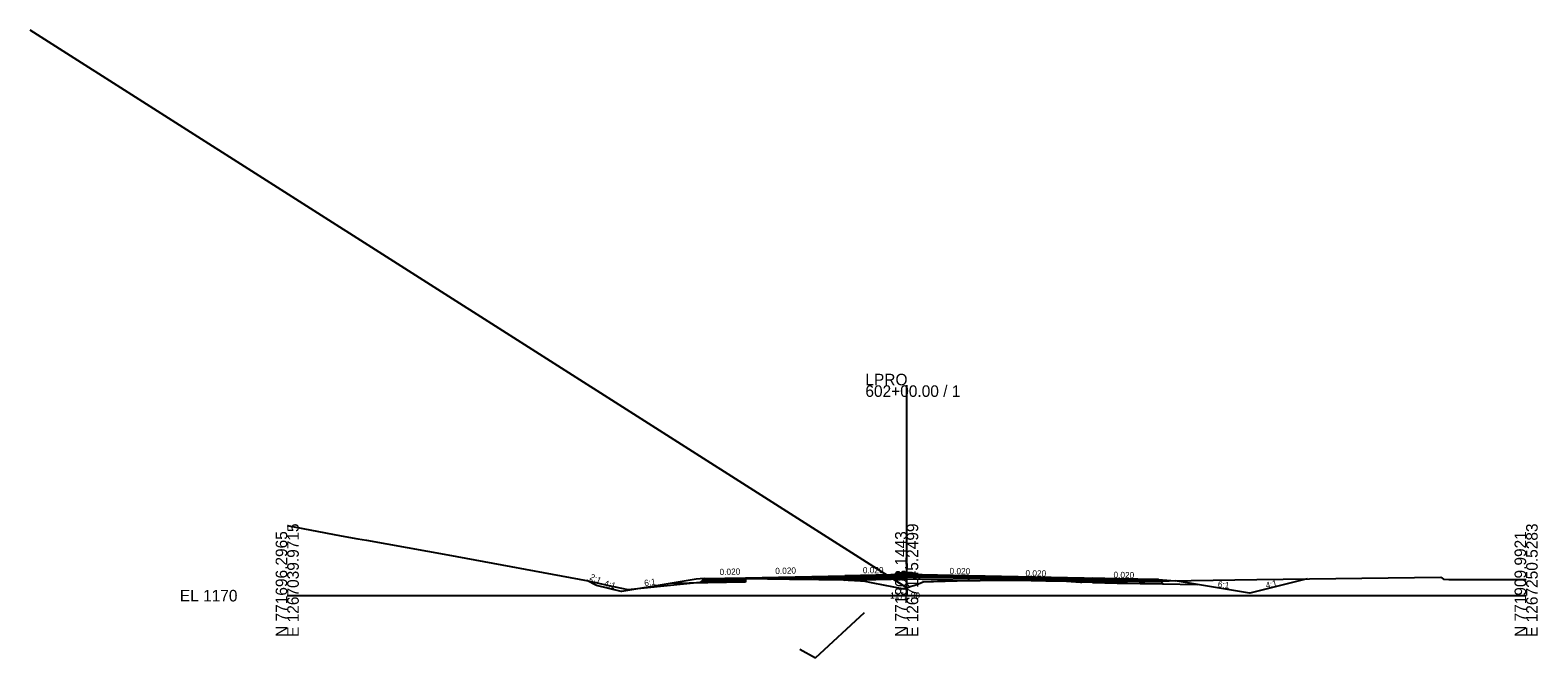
# Model space of a CAD drawing. Extents: x -3833 to 1267678, y -522 to 773248.
# Drawn here: x 937.8 to 1302.8, y 2984.9 to 3137 of the extents above; entities that cross this region are included whole.
import ezdxf

# ---------------------------------------------------------------- set-up
doc = ezdxf.new("R2010")
doc.units = 0
for name, color, linetype in [('Exist Cross Section Cell', 7, 'Continuous'), ('Exist XS Center Line Elevation Label', 7, 'Continuous'), ('Exist XS Ground Line', 7, 'Continuous'), ('Prop CMT DNC', 7, 'Continuous'), ('Prop CMT Pvmt Course 1', 7, 'Continuous'), ('Prop CMT Pvmt Course 2', 7, 'Continuous'), ('Prop CMT Pvmt Course 3', 7, 'Continuous'), ('Prop CMT Pvmt Course 4', 7, 'Continuous'), ('Prop CMT Shld Paved Course 1', 7, 'Continuous'), ('Prop CMT Shld Paved Course 2', 7, 'Continuous'), ('Prop CMT Shld Paved Course 4', 7, 'Continuous'), ('Prop CMT Slope Grass', 7, 'Continuous'), ('Prop CMT Subgrade Earthwork', 7, 'Continuous'), ('Prop Conc Curb and Gutter', 7, 'Continuous'), ('Prop Corridor Mesh Bottom', 7, 'Continuous'), ('Prop XS Ditch Slope Text', 7, 'Continuous'), ('Prop XS Finish Grade', 7, 'Continuous'), ('Prop XS SE Text', 7, 'Continuous'), ('Scratch_Level_1', 7, 'Continuous'), ('Scratch_Level_5', 7, 'Continuous')]:
    doc.layers.add(name, color=color, linetype=linetype)

msp = doc.modelspace()

# ---------------------------------------------------------------- linework, layer by layer
at = {"layer": 'Exist Cross Section Cell'}
for p, q in [((1150, 3000), (1150, 3050.94)), ((1000, 3000), (1150, 3000)), ((1150, 3000), (1300, 3000))]:
    msp.add_line(p, q, dxfattribs=at)
at = {"layer": 'Exist XS Ground Line'}
for p, q in [((1000, 3016.98), (1013.1, 3014.52)), ((1013.1, 3014.52), (1017.12, 3013.79)), ((1017.12, 3013.79), (1019.2, 3013.47)), ((1019.2, 3013.47), (1038.86, 3009.86)), ((1038.86, 3009.86), (1072.85, 3003.6)), ((1072.85, 3003.6), (1077.84, 3002.43)), ((1077.84, 3002.43), (1082.49, 3001.48)), ((1082.49, 3001.48), (1100.75, 3003.38)), ((1100.75, 3003.38), (1104.96, 3003.76)), ((1104.96, 3003.76), (1106.21, 3003.95)), ((1106.21, 3003.95), (1106.62, 3003.97)), ((1106.62, 3003.97), (1111, 3004.18)), ((1111, 3004.18), (1121.63, 3004.03)), ((1121.63, 3004.03), (1122.75, 3004.01)), ((1122.75, 3004.01), (1134.73, 3003.8)), ((1134.73, 3003.8), (1135.81, 3003.77)), ((1135.81, 3003.77), (1138.81, 3003.63)), ((1138.81, 3003.63), (1139.44, 3003.57)), ((1139.44, 3003.57), (1141.84, 3003.14)), ((1141.84, 3003.14), (1149.34, 3001.69)), ((1149.34, 3001.69), (1150, 3001.9)), ((1150, 3001.9), (1151.1, 3002.26)), ((1151.1, 3002.26), (1151.76, 3002.45)), ((1151.76, 3002.45), (1152.86, 3002.88)), ((1152.86, 3002.88), (1154.02, 3003.31)), ((1154.02, 3003.31), (1155.92, 3003.4)), ((1155.92, 3003.4), (1156.46, 3003.42)), ((1156.46, 3003.42), (1162.26, 3003.57)), ((1162.26, 3003.57), (1164.74, 3003.64)), ((1164.74, 3003.64), (1167.77, 3003.67)), ((1167.77, 3003.67), (1176.6, 3003.75)), ((1176.6, 3003.75), (1183.66, 3003.59)), ((1183.66, 3003.59), (1188.69, 3003.48)), ((1188.69, 3003.48), (1192.07, 3003.27)), ((1192.07, 3003.27), (1192.42, 3003.25)), ((1192.42, 3003.25), (1234.82, 3003.9)), ((1234.82, 3003.9), (1279.31, 3004.46)), ((1279.31, 3004.46), (1279.96, 3003.96)), ((1279.96, 3003.96), (1281.26, 3003.94)), ((1281.26, 3003.94), (1284.65, 3003.94)), ((1284.65, 3003.94), (1284.99, 3003.94)), ((1284.99, 3003.94), (1300, 3003.93))]:
    msp.add_line(p, q, dxfattribs=at)
at = {"layer": 'Prop CMT Pvmt Course 1'}
for p, q in [((1111, 3004.34), (1135, 3004.82)), ((1135, 3004.82), (1135, 3004.82)), ((1135, 3004.82), (1135, 3004.82)), ((1135, 3004.82), (1135, 3004.57)), ((1146.95, 3005.06), (1146.2, 3005.04)), ((1146.2, 3005.04), (1146.2, 3004.79)), ((1146.2, 3005.04), (1146.2, 3005.04)), ((1146.2, 3004.79), (1146.95, 3004.81)), ((1146.2, 3004.79), (1146.2, 3004.79)), ((1146.95, 3004.81), (1146.95, 3005.06)), ((1152.25, 3004.82), (1152.25, 3005.07)), ((1152.25, 3005.07), (1152.82, 3005.06)), ((1152.82, 3004.81), (1152.25, 3004.82)), ((1152.82, 3005.06), (1153, 3005.06)), ((1153, 3004.81), (1152.82, 3004.81)), ((1153, 3005.06), (1153, 3004.81)), ((1201, 3004.1), (1165, 3004.82)), ((1165, 3004.82), (1165, 3004.82)), ((1165, 3004.82), (1165, 3004.82)), ((1165, 3004.82), (1165, 3004.57)), ((1135, 3004.57), (1111, 3004.09)), ((1111, 3004.09), (1111, 3004.34)), ((1111, 3004.34), (1111, 3004.34)), ((1135, 3004.57), (1135, 3004.57)), ((1165, 3004.57), (1195, 3003.97)), ((1165, 3004.57), (1165, 3004.57)), ((1195, 3004.22), (1195, 3003.97)), ((1201, 3004.1), (1195, 3004.22)), ((1195, 3003.97), (1195, 3004.22)), ((1195, 3004.22), (1195, 3004.22)), ((1195, 3004.22), (1195, 3004.22)), ((1195, 3004.22), (1201, 3004.1)), ((1195, 3003.97), (1201, 3003.85)), ((1201, 3003.85), (1201, 3004.1))]:
    msp.add_line(p, q, dxfattribs=at)
at = {"layer": 'Prop CMT Pvmt Course 2'}
for p, q in [((1150, 3004.87), (1135, 3004.57)), ((1146.95, 3004.81), (1146.2, 3004.79)), ((1146.2, 3004.79), (1146.2, 3004.54)), ((1146.2, 3004.79), (1146.2, 3004.79)), ((1146.95, 3004.56), (1146.95, 3004.81)), ((1165, 3004.57), (1150, 3004.87)), ((1150, 3004.87), (1150, 3004.87)), ((1150, 3004.87), (1150, 3004.87)), ((1152.25, 3004.57), (1152.25, 3004.82)), ((1152.25, 3004.82), (1152.82, 3004.81)), ((1152.82, 3004.81), (1153, 3004.81)), ((1153, 3004.81), (1153, 3004.56)), ((1135, 3004.57), (1135, 3004.57)), ((1135, 3004.57), (1135, 3004.24)), ((1135, 3004.24), (1150, 3004.54)), ((1135, 3004.24), (1135, 3004.24)), ((1146.2, 3004.54), (1146.2, 3004.54)), ((1150, 3004.54), (1150, 3004.54)), ((1150, 3004.54), (1150, 3004.54)), ((1150, 3004.54), (1165, 3004.24)), ((1165, 3004.24), (1165, 3004.57)), ((1165, 3004.57), (1165, 3004.57)), ((1165, 3004.24), (1165, 3004.24)), ((1195, 3003.97), (1195, 3003.64)), ((1201, 3003.85), (1195, 3003.97)), ((1195, 3003.64), (1201, 3003.52)), ((1201, 3003.52), (1201, 3003.85))]:
    msp.add_line(p, q, dxfattribs=at)
at = {"layer": 'Prop CMT Pvmt Course 3'}
for p, q in [((1146.2, 3004.54), (1146.2, 3004.17)), ((1146.2, 3004.54), (1146.2, 3004.54)), ((1146.2, 3004.17), (1146.2, 3004.17)), ((1146.95, 3004.18), (1146.95, 3004.56)), ((1152.25, 3004.2), (1152.25, 3004.57)), ((1153, 3004.56), (1153, 3004.18))]:
    msp.add_line(p, q, dxfattribs=at)
at = {"layer": 'Prop CMT Pvmt Course 4'}
for p, q in [((1135, 3003.78), (1150.01, 3004.08)), ((1135, 3003.78), (1135, 3003.79)), ((1146.2, 3004.17), (1146.2, 3004)), ((1146.2, 3004.17), (1146.2, 3004.17)), ((1146.95, 3004.02), (1146.95, 3004.18)), ((1149.99, 3004.08), (1165, 3003.78)), ((1152.25, 3004.03), (1152.25, 3004.2)), ((1153, 3004.18), (1153, 3004.02)), ((1195, 3003.64), (1195, 3003.18)), ((1201, 3003.52), (1195, 3003.64)), ((1195, 3003.18), (1201, 3003.06)), ((1201, 3003.06), (1201, 3003.52))]:
    msp.add_line(p, q, dxfattribs=at)
at = {"layer": 'Prop CMT Shld Paved Course 1'}
for p, q in [((1150, 3005.12), (1135, 3004.82)), ((1135, 3004.57), (1150, 3004.87)), ((1135, 3004.82), (1135, 3004.82)), ((1135, 3004.82), (1135, 3004.57)), ((1149.99, 3005.16), (1149.99, 3005.16)), ((1149.99, 3005.16), (1149.99, 3005.16)), ((1149.99, 3004.91), (1149.99, 3004.91)), ((1165, 3004.82), (1150, 3005.12)), ((1150, 3005.12), (1150, 3005.12)), ((1150, 3005.12), (1150, 3005.12)), ((1150, 3004.87), (1150, 3004.87)), ((1150, 3004.87), (1150, 3004.87)), ((1150, 3004.87), (1165, 3004.57)), ((1165, 3004.57), (1165, 3004.82)), ((1165, 3004.82), (1165, 3004.82)), ((1100.74, 3003.88), (1101, 3004.14)), ((1111, 3004.09), (1100.74, 3003.88)), ((1101, 3004.14), (1111, 3004.34)), ((1101, 3004.14), (1101, 3004.14)), ((1111, 3004.34), (1111, 3004.34)), ((1111, 3004.34), (1111, 3004.34)), ((1111, 3004.34), (1111, 3004.09)), ((1111, 3004.09), (1111, 3004.09)), ((1201, 3004.1), (1201, 3003.85)), ((1211, 3003.9), (1201, 3004.1)), ((1201, 3003.85), (1211.26, 3003.64)), ((1211.26, 3003.64), (1211, 3003.9))]:
    msp.add_line(p, q, dxfattribs=at)
at = {"layer": 'Prop CMT Shld Paved Course 2'}
for p, q in [((1100.4, 3003.54), (1100.74, 3003.88)), ((1111, 3003.76), (1100.4, 3003.54)), ((1100.74, 3003.88), (1111, 3004.09)), ((1100.74, 3003.88), (1100.74, 3003.88)), ((1121.63, 3004.3), (1111, 3004.09)), ((1111, 3004.09), (1113.78, 3004.14)), ((1111, 3004.09), (1111, 3004.09)), ((1111, 3004.09), (1111, 3004.09)), ((1111, 3004.09), (1111, 3003.76)), ((1111, 3004.09), (1111, 3004.09)), ((1111, 3004.09), (1111, 3004.09)), ((1111, 3004.09), (1111, 3004.09)), ((1111, 3003.76), (1111, 3003.76)), ((1113.78, 3004.14), (1113.78, 3004.14)), ((1113.78, 3004.14), (1113.78, 3004.14)), ((1113.78, 3004.14), (1121.63, 3004.03)), ((1122.75, 3004.32), (1121.63, 3004.3)), ((1121.63, 3004.3), (1121.63, 3004.3)), ((1121.63, 3004.03), (1121.63, 3004.03)), ((1121.63, 3004.03), (1122.75, 3004.01)), ((1134.73, 3004.56), (1122.75, 3004.32)), ((1122.75, 3004.32), (1122.75, 3004.32)), ((1122.75, 3004.01), (1123.37, 3004)), ((1123.37, 3004), (1134.73, 3004.23)), ((1123.37, 3004), (1123.37, 3004)), ((1123.37, 3004), (1123.37, 3004)), ((1135, 3004.57), (1134.73, 3004.56)), ((1134.73, 3004.56), (1134.73, 3004.56)), ((1134.73, 3004.23), (1135, 3004.24)), ((1134.73, 3004.23), (1134.73, 3004.23)), ((1135, 3003.78), (1135, 3004.57)), ((1135, 3004.57), (1135, 3004.57)), ((1167.77, 3004.51), (1165, 3004.57)), ((1165, 3004.57), (1165, 3004.57)), ((1165, 3004.57), (1165, 3003.78)), ((1165, 3004.24), (1167.77, 3004.18)), ((1176.6, 3004.34), (1167.77, 3004.51)), ((1167.77, 3004.51), (1167.77, 3004.51)), ((1167.77, 3004.18), (1167.77, 3004.18)), ((1167.77, 3004.18), (1176.6, 3004)), ((1183.66, 3004.2), (1176.6, 3004.34)), ((1176.6, 3004.34), (1176.6, 3004.34)), ((1176.6, 3004), (1176.6, 3004)), ((1176.6, 3004), (1183.66, 3003.86)), ((1188.69, 3004.09), (1183.66, 3004.2)), ((1183.66, 3004.2), (1183.66, 3004.2)), ((1183.66, 3003.86), (1183.66, 3003.86)), ((1183.66, 3003.86), (1188.69, 3003.76)), ((1192.07, 3004.03), (1188.69, 3004.09)), ((1188.69, 3004.09), (1188.69, 3004.09)), ((1188.69, 3004.09), (1188.69, 3004.09)), ((1188.69, 3003.76), (1188.69, 3003.76)), ((1188.69, 3003.76), (1188.69, 3003.76)), ((1188.69, 3003.76), (1192.07, 3003.69)), ((1192.42, 3004.02), (1192.07, 3004.03)), ((1192.07, 3004.03), (1192.07, 3004.03)), ((1192.07, 3003.69), (1192.07, 3003.69)), ((1192.07, 3003.69), (1192.42, 3003.69)), ((1195, 3003.97), (1192.42, 3004.02)), ((1192.42, 3004.02), (1192.42, 3004.02)), ((1192.42, 3003.69), (1192.42, 3003.69)), ((1192.42, 3003.69), (1195, 3003.64)), ((1195, 3003.64), (1195, 3003.97)), ((1195, 3003.97), (1195, 3003.97)), ((1201, 3003.85), (1201, 3003.52)), ((1211.26, 3003.64), (1201, 3003.85)), ((1201, 3003.52), (1211.59, 3003.31)), ((1211.59, 3003.31), (1211.26, 3003.64))]:
    msp.add_line(p, q, dxfattribs=at)
at = {"layer": 'Prop CMT Shld Paved Course 4'}
for p, q in [((1099.94, 3003.08), (1100.4, 3003.54)), ((1111, 3003.3), (1099.94, 3003.08)), ((1100.4, 3003.54), (1100.9, 3003.55)), ((1100.9, 3003.55), (1111, 3003.76)), ((1111, 3003.76), (1111, 3003.3)), ((1201, 3003.52), (1201, 3003.06)), ((1211.09, 3003.32), (1201, 3003.52)), ((1201, 3003.06), (1212.06, 3002.84)), ((1211.59, 3003.31), (1211.09, 3003.32)), ((1212.06, 3002.84), (1211.59, 3003.31))]:
    msp.add_line(p, q, dxfattribs=at)
at = {"layer": 'Prop CMT Slope Grass'}
for p, q in [((1099, 3003.98), (1092.72, 3002.93)), ((1101, 3004.14), (1099, 3003.98)), ((1211, 3003.9), (1215, 3003.58)), ((1220.43, 3002.67), (1215, 3003.58))]:
    msp.add_line(p, q, dxfattribs=at)
at = {"layer": 'Prop CMT Subgrade Earthwork'}
for p, q in [((1111, 3003.3), (1092.72, 3002.93)), ((1111, 3004.18), (1111, 3003.3)), ((1150.01, 3004.08), (1135, 3003.78)), ((1135, 3003.78), (1135, 3003.79)), ((1149.99, 3004.08), (1165, 3003.78)), ((1165, 3003.78), (1165, 3003.64)), ((1195, 3003.29), (1195, 3003.18)), ((1195, 3003.18), (1220.43, 3002.67))]:
    msp.add_line(p, q, dxfattribs=at)
at = {"layer": 'Prop Conc Curb and Gutter'}
for p, q in [((1147.2, 3005.14), (1147.21, 3005.3)), ((1147.2, 3005.14), (1147.2, 3005.01)), ((1147.2, 3005.01), (1150, 3005.01)), ((1147.21, 3005.3), (1147.91, 3005.54)), ((1147.91, 3005.54), (1150, 3005.58)), ((1151.24, 3005.55), (1150, 3005.58)), ((1152, 3005.01), (1150, 3005.01)), ((1151.99, 3005.3), (1151.24, 3005.55)), ((1152, 3005.13), (1151.99, 3005.3)), ((1152, 3005.13), (1152, 3005.01)), ((1152.25, 3005.07), (1152.25, 3004.95))]:
    msp.add_line(p, q, dxfattribs=at)
at = {"layer": 'Prop Corridor Mesh Bottom'}
for p, q in [((1135, 3004.82), (1135, 3004.57)), ((1165, 3004.82), (1165, 3004.57)), ((1111, 3004.34), (1111, 3004.09)), ((1201, 3004.1), (1201, 3003.85))]:
    msp.add_line(p, q, dxfattribs=at)
at = {"layer": 'Prop XS Finish Grade'}
for p, q in [((1074.9, 3002.48), (1072.54, 3003.66)), ((1080.9, 3000.98), (1074.9, 3002.48)), ((1092.72, 3002.93), (1081, 3000.98)), ((1215, 3003.58), (1215, 3003.58)), ((1233, 3000.58), (1220.43, 3002.67)), ((1246.99, 3004.05), (1233.1, 3000.58)), ((1080.95, 3000.98), (1080.9, 3000.98)), ((1081, 3000.98), (1080.95, 3000.98)), ((1233.05, 3000.58), (1233, 3000.58)), ((1233, 3000.58), (1233, 3000.58)), ((1233.1, 3000.58), (1233.05, 3000.58)), ((1233.1, 3000.58), (1233.1, 3000.58)), ((1233.1, 3000.58), (1233.1, 3000.58))]:
    msp.add_line(p, q, dxfattribs=at)
at = {"layer": 'Scratch_Level_1'}
msp.add_line((1150, 3001.9), (937.75, 3136.96), dxfattribs=at)
at = {"layer": 'Scratch_Level_5'}
for p, q in [((1127.93, 2984.94), (1139.79, 2995.96)), ((1124.15, 2987.04), (1127.93, 2984.94))]:
    msp.add_line(p, q, dxfattribs=at)

# ---------------------------------------------------------------- texts
at = {"layer": 'Exist Cross Section Cell'}
for s, p in [('LPRO', (1140, 3050.94)), ('602+00.00 / 1', (1140, 3048.14)), ('EL 1170', (974, 2998.6))]:
    msp.add_text(s, height=2.8, dxfattribs=at).set_placement(p)
for s, p in [('E 1267039.9715', (1002.8, 2990)), ('E 1267145.2499', (1152.8, 2990)), ('E 1267250.5283', (1302.8, 2990)), ('N 771696.2965', (1000, 2990)), ('N 771803.1443', (1150, 2990)), ('N 771909.9921', (1300, 2990))]:
    msp.add_text(s, height=2.8, rotation=90, dxfattribs=at).set_placement(p)
at = {"layer": 'Exist XS Center Line Elevation Label'}
msp.add_text('1171.90', height=1.5, dxfattribs=at).set_placement((1145.98, 2999.31))
at = {"layer": 'Prop CMT DNC'}
for p in [(1135, 3004.82), (1135, 3004.82), (1149.99, 3005.16), (1150, 3005.12), (1165, 3004.82), (1165, 3004.82), (1101, 3004.14), (1111, 3004.34), (1111, 3004.34), (1201, 3004.1), (1201, 3004.1), (1211, 3003.9), (1246.99, 3004.05), (1080.95, 3000.98), (1081, 3000.98), (1233, 3000.58), (1233.05, 3000.58)]:
    msp.add_text('X', height=0.00025, dxfattribs=at).set_placement(p)
at = {"layer": 'Prop XS Ditch Slope Text'}
for s, rotation, p in [('2:1', 334.1731, (1073.09, 3004.04)), ('4:1', 343.7547, (1076.61, 3002.37)), ('6:1', 9.0286, (1086.57, 3002.28)), ('6:1', 352.0901, (1225.27, 3002.09)), ('4:1', 14.1789, (1237.13, 3001.71))]:
    msp.add_text(s, height=1.5, rotation=rotation, dxfattribs=at).set_placement(p)
at = {"layer": 'Prop XS SE Text'}
for rotation, p in [(1.397, (1104.71, 3004.98)), (1.397, (1118.2, 3005.23)), (0.2693, (1139.38, 3005.42)), (358.8542, (1160.37, 3005.24)), (358.8542, (1178.75, 3004.72)), (358.8542, (1200.07, 3004.31))]:
    msp.add_text('0.020', height=1.5, rotation=rotation, dxfattribs=at).set_placement(p)

doc.saveas('drawing.dxf')
